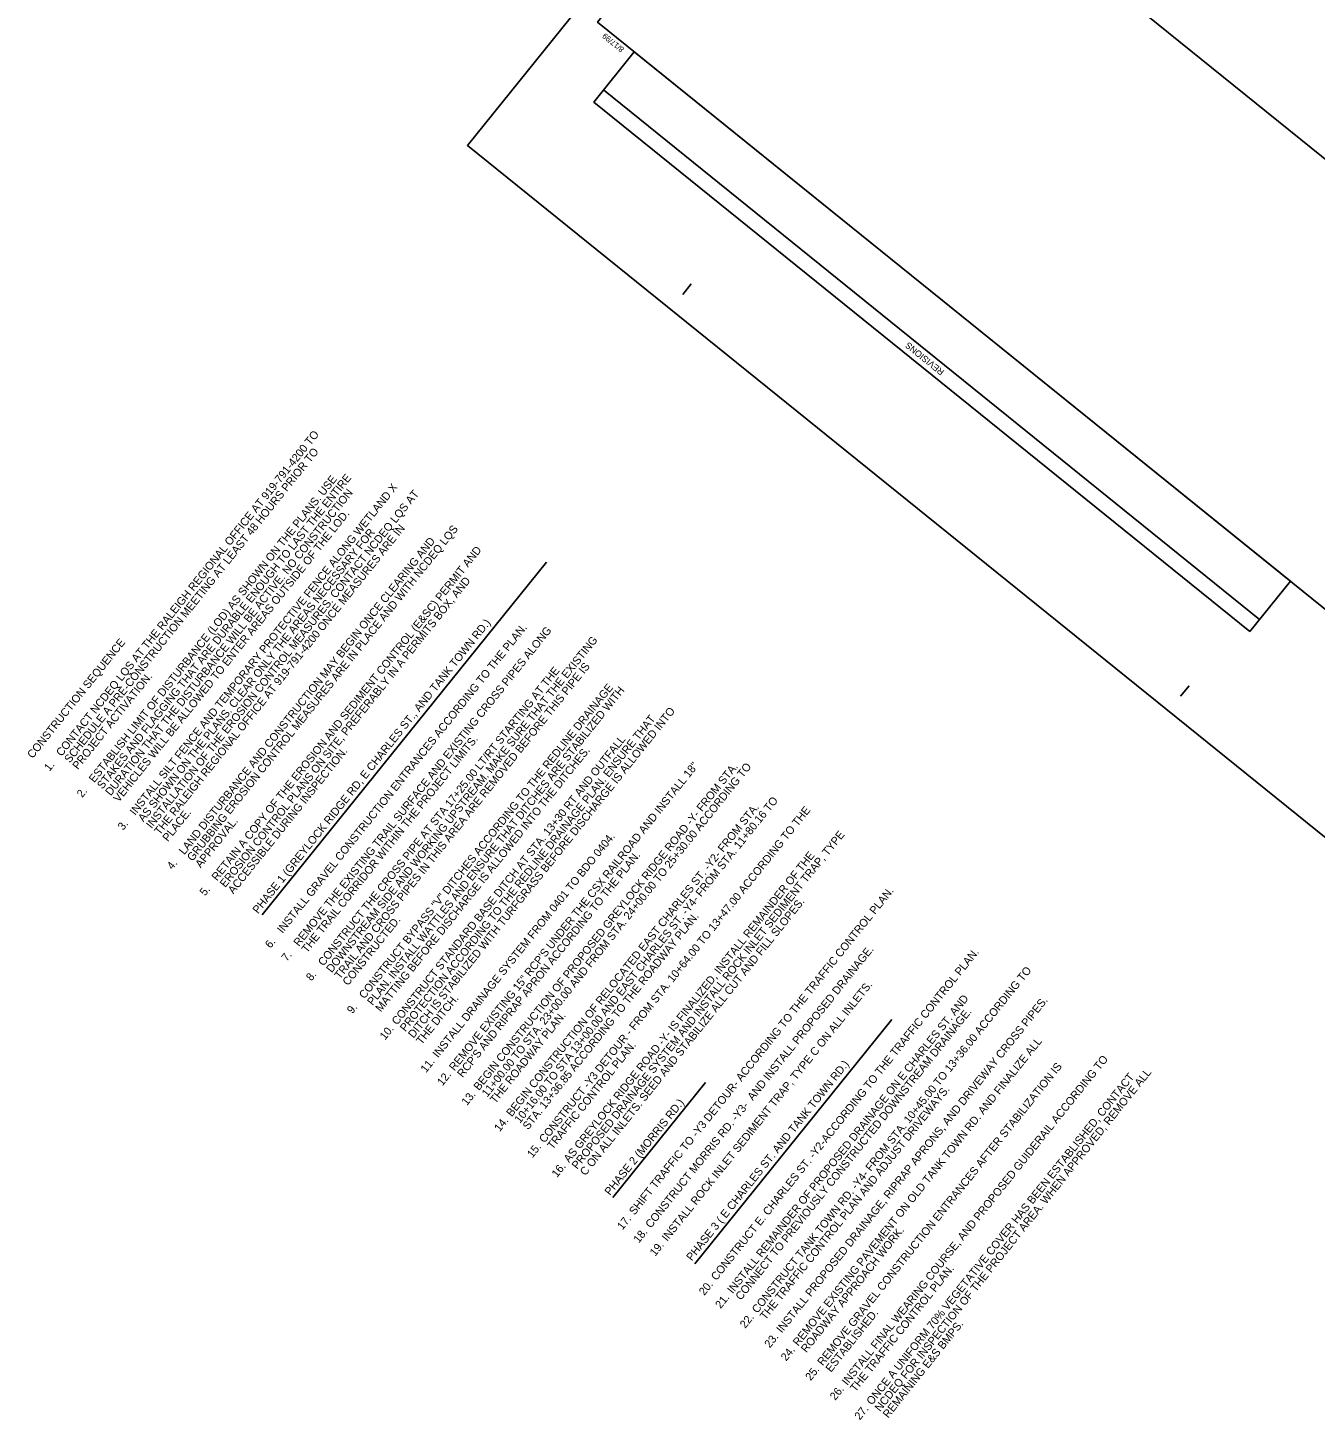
# Model space of a CAD drawing. Extents: x 1487432 to 1489935, y 497862 to 500368.
# Drawn here: x 1487432 to 1488640, y 497862 to 499167 of the extents above; entities that cross this region are included whole.
import ezdxf

# ---------------------------------------------------------------- set-up
doc = ezdxf.new("R2010")
doc.units = 0
for name, color, linetype in [('Level 10', 7, 'Continuous'), ('Level 18', 7, 'Continuous'), ('Level 19', 7, 'Continuous'), ('Level 32', 7, 'Continuous'), ('Level 5', 7, 'Continuous')]:
    doc.layers.add(name, color=color, linetype=linetype)

msp = doc.modelspace()

# ---------------------------------------------------------------- linework, layer by layer
at = {"layer": 'Level 10'}
msp.add_lwpolyline([(1488183, 499420.5), (1488642.3, 499990), (1489445.2, 499342.5), (1488985.9, 498773)], close=True, dxfattribs=at)
at = {"layer": 'Level 18'}
msp.add_line((1488587.8, 498612.8), (1487972.3, 499109.2), dxfattribs=at)
msp.add_lwpolyline([(1488578.7, 498601.5), (1487963.2, 499097.8), (1488001.2, 499145), (1488616.7, 498648.6)], close=True, dxfattribs=at)
at = {"layer": 'Level 19'}
for p, q in [((1488046.7, 498917.5), (1488054.5, 498927.3)), ((1488513.7, 498540.9), (1488521.6, 498550.6))]:
    msp.add_line(p, q, dxfattribs=at)
for points in [[(1488908.3, 500340.5), (1487966.7, 499172.8), (1488784, 498513.7), (1489725.7, 499681.3)], [(1488784, 498513.7), (1487966.7, 499172.8), (1488782.7, 500184.7), (1488899.5, 500090.5), (1489025.1, 500246.2), (1489725.7, 499681.3)]]:
    msp.add_lwpolyline(points, close=True, dxfattribs=at)
at = {"layer": 'Level 32'}
for p, q in [((1487652, 498335.7), (1487918.7, 498666.4)), ((1488058.1, 498008.3), (1488242.8, 498237.4)), ((1487980.9, 498070.5), (1488067.9, 498178.4))]:
    msp.add_line(p, q, dxfattribs=at)
at = {"layer": 'Level 5'}
msp.add_lwpolyline([(1488697, 498369.9), (1489753.8, 499680.4), (1488901.5, 500367.8), (1487844.7, 499057.3)], close=True, dxfattribs=at)

# ---------------------------------------------------------------- texts
at = {"layer": 'Level 10'}
for s, p in [('CONTACT NCDEQ LQS AT THE RALEIGH REGIONAL OFFICE AT 919-791-4200 TO ', (1487463.9, 498483.7)), ('SCHEDULE A PRE-CONSTRUCTION MEETING AT LEAST 48 HOURS PRIOR TO ', (1487471.6, 498477.5)), ('STAKES AND FLAGGING THAT ARE DURABLE ENOUGH TO LAST THE ENTIRE ', (1487502.3, 498453)), ('ESTABLISH LIMIT OF DISTURBANCE (LOD) AS SHOWN ON THE PLANS. USE ', (1487494.6, 498459.1)), ('DURATION THAT THE DISTURBANCE WILL BE ACTIVE. NO CONSTRUCTION ', (1487510, 498446.8)), ('INSTALL SILT FENCE AND TEMPORARY PROTECTIVE FENCE ALONG WETLAND X ', (1487533, 498428.4)), ('INSTALLATION OF THE EROSION CONTROL MEASURES. CONTACT NCDEQ LQS AT ', (1487548.3, 498416.1)), ('VEHICLES WILL BE ALLOWED TO ENTER AREAS OUTSIDE OF THE LOD.', (1487517.6, 498440.7)), ('AS SHOWN ON THE PLANS. CLEAR ONLY THE AREAS NECESSARY FOR ', (1487540.7, 498422.3)), ('THE RALEIGH REGIONAL OFFICE AT 919-791-4200 ONCE MEASURES ARE IN ', (1487556, 498410)), ('GRUBBING EROSION CONTROL MEASURES ARE IN PLACE AND WITH NCDEQ LQS ', (1487586.7, 498385.4)), ('LAND DISTURBANCE AND CONSTRUCTION MAY BEGIN ONCE CLEARING AND ', (1487579.1, 498391.5)), ('RETAIN A COPY OF THE EROSION AND SEDIMENT CONTROL (E&SC) PERMIT AND ', (1487609.8, 498367)), ('EROSION CONTROL PLANS ON SITE, PREFERABLY IN A PERMITS BOX, AND ', (1487617.5, 498360.8)), ('PHASE 1 (GREYLOCK RIDGE RD, E CHARLES ST., AND TANK TOWN RD.)', (1487648.2, 498336.2)), ('INSTALL GRAVEL CONSTRUCTION ENTRANCES ACCORDING TO THE PLAN.', (1487671.2, 498317.8)), ('REMOVE THE EXISTING TRAIL SURFACE AND EXISTING CROSS PIPES ALONG ', (1487686.6, 498305.5)), ('CONSTRUCTION SEQUENCE', (1487436.8, 498481.8)), ('DOWNSTREAM SIDE AND WORKING UPSTREAM. MAKE SURE THAT THE EXISTING ', (1487717.3, 498280.9)), ('CONSTRUCT THE CROSS PIPE AT STA 17+25.00 LT/RT STARTING AT THE ', (1487709.6, 498287.1)), ('TRAIL AND CROSS PIPES IN THIS AREA ARE REMOVED BEFORE THIS PIPE IS ', (1487725, 498274.8)), ('PROJECT ACTIVATION.', (1487479.2, 498471.4)), ('CONSTRUCT BYPASS "V" DITCHES ACCORDING TO THE REDLINE DRAINAGE ', (1487748, 498256.4)), ('PLAN. INSTALL WATTLES AND ENSURE THAT DITCHES ARE STABILIZED WITH ', (1487755.7, 498250.2)), ('DITCH IS STABILIZED WITH TURFGRASS BEFORE DISCHARGE IS ALLOWED INTO ', (1487794.1, 498219.5)), ('PROTECTION ACCORDING TO THE REDLINE DRAINAGE PLAN. ENSURE THAT ', (1487786.4, 498225.6)), ('THE TRAIL CORRIDOR WITHIN THE PROJECT LIMITS.', (1487694.2, 498299.4)), ('CONSTRUCT STANDARD BASE DITCH AT STA. 13+30 RT AND OUTFALL ', (1487778.7, 498231.8)), ('ACCESSIBLE DURING INSPECTION.', (1487625.1, 498354.7)), ('MATTING BEFORE DISCHARGE IS ALLOWED INTO THE DITCHES.', (1487763.4, 498244.1)), ('1.', (1487452.6, 498469.7)), ('REMOVE EXISTING 15" RCP\'S UNDER THE CSX RAILROAD AND INSTALL 18" ', (1487832.5, 498188.8)), ('BEGIN CONSTRUCTION OF PROPOSED GREYLOCK RIDGE ROAD -Y- FROM STA. ', (1487855.5, 498170.4)), ('11+00.00 TO STA. 23+00.00 AND FROM STA. 24+00.00 TO 25+30.00 ACCORDING TO ', (1487863.2, 498164.2)), ('2.', (1487483.3, 498445.1)), ('BEGIN CONSTRUCTION OF RELOCATED EAST CHARLES ST. -Y2- FROM STA. ', (1487886.2, 498145.8)), ('10+16.00 TO STA 13+00.00 AND EAST CHARLES ST. -Y4- FROM STA. 11+80.16 TO ', (1487893.9, 498139.6)), ('CONSTRUCT -Y3 DETOUR - FROM STA. 10+64.00 TO 13+47.00 ACCORDING TO THE ', (1487916.9, 498121.2)), ('3.', (1487521.7, 498414.4)), ('PLACE.', (1487563.7, 498403.8)), ('APPROVAL.', (1487594.4, 498379.2)), ('INSTALL DRAINAGE SYSTEM FROM 0401 TO BDO 0404.', (1487817.1, 498201.1)), ('PROPOSED DRAINAGE SYSTEM AND INSTALL ROCK INLET SEDIMENT TRAP, TYPE ', (1487947.6, 498096.6)), ('4.', (1487567.8, 498377.5)), ("RCP'S AND RIPRAP APRON ACCORDING TO THE PLAN.", (1487840.1, 498182.6)), ('AS GREYLOCK RIDGE ROAD -Y- IS FINALIZED, INSTALL REMAINDER OF THE ', (1487940, 498102.8)), ('5.', (1487598.5, 498352.9)), ('SHIFT TRAFFIC TO -Y3 DETOUR- ACCORDING TO THE TRAFFIC CONTROL PLAN.', (1488001.4, 498053.6)), ('C ON ALL INLETS. SEED AND STABILIZE ALL CUT AND FILL SLOPES.', (1487955.3, 498090.5)), ('CONSTRUCTED.', (1487732.6, 498268.7)), ('STA. 13+36.85 ACCORDING TO THE ROADWAY PLAN.', (1487901.6, 498133.5)), ('6.', (1487659.9, 498303.8)), ('CONSTRUCT MORRIS RD. -Y3-  AND INSTALL PROPOSED DRAINAGE. ', (1488016.7, 498041.3)), ('7.', (1487675.3, 498291.5)), ('CONSTRUCT E. CHARLES ST. -Y2-ACCORDING TO THE TRAFFIC CONTROL PLAN. ', (1488078.2, 497992.2)), ('8.', (1487698.3, 498273.1)), ('CONSTRUCT TANK TOWN RD. -Y4- FROM STA. 10+45.00 TO 13+36.00 ACCORDING TO ', (1488116.6, 497961.5)), ('INSTALL ROCK INLET SEDIMENT TRAP, TYPE C ON ALL INLETS.', (1488032.1, 498029)), ('THE DITCH. ', (1487801.7, 498213.4)), ('INSTALL REMAINDER OF PROPOSED DRAINAGE ON E CHARLES ST. AND ', (1488093.5, 497979.9)), ('INSTALL PROPOSED DRAINAGE, RIPRAP APRONS, AND DRIVEWAY CROSS PIPES. ', (1488139.6, 497943)), ('9.', (1487736.7, 498242.4)), ('THE ROADWAY PLAN.', (1487870.9, 498158.1)), ('CONNECT TO PREVIOUSLY CONSTRUCTED DOWNSTREAM DRAINAGE.', (1488101.2, 497973.7)), ('10.', (1487767.4, 498217.8)), ('TRAFFIC CONTROL PLAN.', (1487924.6, 498115.1)), ('REMOVE EXISTING PAVEMENT ON OLD TANK TOWN RD. AND FINALIZE ALL ', (1488155, 497930.7)), ('INSTALL FINAL WEARING COURSE, AND PROPOSED GUIDERAIL ACCORDING TO ', (1488201, 497893.9)), ('11.', (1487805.8, 498187.1)), ('12.', (1487821.2, 498174.8)), ('PHASE 3 ( E CHARLES ST. AND TANK TOWN RD.)', (1488055.1, 498010.6)), ('REMOVE GRAVEL CONSTRUCTION ENTRANCES AFTER STABILIZATION IS ', (1488178, 497912.3)), ('ONCE A UNIFORM 70% VEGETATIVE COVER HAS BEEN ESTABLISHED, CONTACT ', (1488224.1, 497875.4)), ('NCDEQ FOR INSPECTION OF THE PROJECT AREA. WHEN APPROVED, REMOVE ALL ', (1488231.8, 497869.3)), ('13.', (1487844.2, 498156.3)), ('PHASE 2 (MORRIS RD.)', (1487978.4, 498072)), ('THE TRAFFIC CONTROL PLAN AND ADJUST DRIVEWAYS.', (1488124.2, 497955.3)), ('14.', (1487874.9, 498131.8)), ('15.', (1487905.6, 498107.2)), ('16.', (1487928.7, 498088.8)), ('17.', (1487990.1, 498039.6)), ('18.', (1488005.4, 498027.3)), ('ROADWAY APPROACH WORK.', (1488162.6, 497924.6)), ('19.', (1488020.8, 498015)), ('THE TRAFFIC CONTROL PLAN.', (1488208.7, 497887.7)), ('20.', (1488066.9, 497978.2)), ('21.', (1488082.2, 497965.9)), ('22.', (1488105.3, 497947.4)), ('ESTABLISHED.', (1488185.7, 497906.2)), ('REMAINING E&S BMPS.', (1488239.4, 497863.2)), ('23.', (1488128.3, 497929)), ('24.', (1488143.7, 497916.7)), ('25.', (1488166.7, 497898.3)), ('26.', (1488189.7, 497879.9)), ('27.', (1488212.8, 497861.4))]:
    msp.add_text(s, height=7.5, rotation=51.3359, dxfattribs=at).set_placement(p)
at = {"layer": 'Level 18'}
msp.add_text('REVISIONS', height=6, rotation=141.1156, dxfattribs=at).set_placement((1488292.5, 498845.8))
at = {"layer": 'Level 19'}
msp.add_text('8/17/99', height=5.25, rotation=141.1157, dxfattribs=at).set_placement((1487992.1, 499148.2))

doc.saveas('drawing.dxf')
